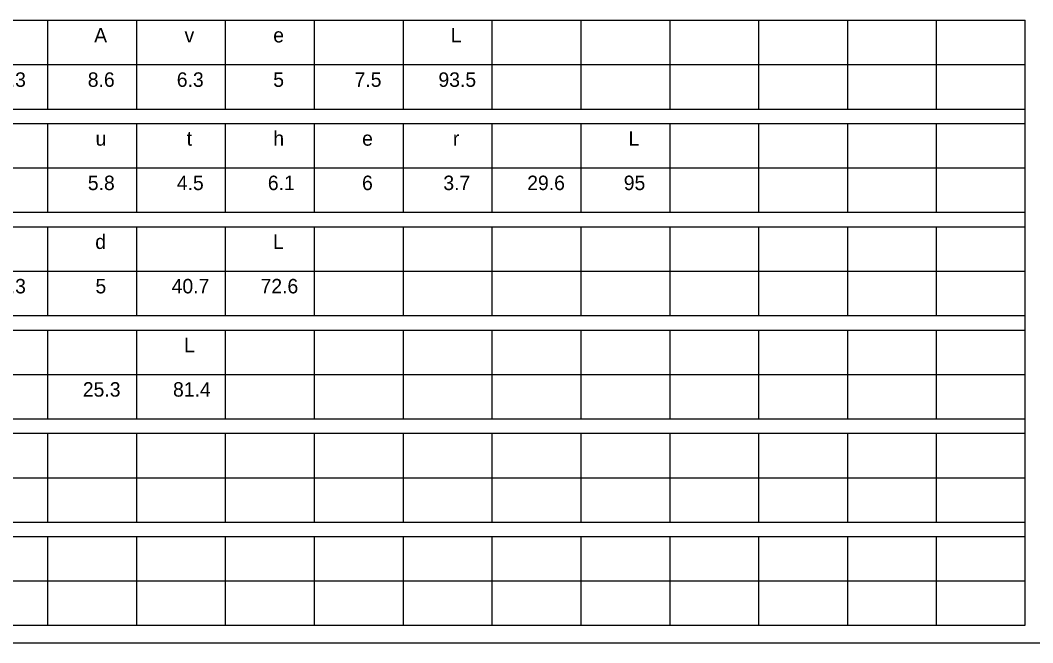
# Model space of a CAD drawing. Extents: x 1274.1 to 1363.1, y 833.5 to 890.6.
# Drawn here: x 1299.62 to 1318.48, y 864.21 to 875.81 of the extents above; entities that cross this region are included whole.
import ezdxf

# ---------------------------------------------------------------- set-up
doc = ezdxf.new("R2010")
doc.units = 0
doc.layers.add('GSSign', color=7, linetype='Continuous')
doc.layers.add('SheetLinesMisc2_dp', color=7, linetype='Continuous')

msp = doc.modelspace()

# ---------------------------------------------------------------- linework, layer by layer
at = {"layer": 'SheetLinesMisc2_dp'}
for p, q in [((1277.644, 875.806), (1318.336, 875.806)), ((1300.127, 875.806), (1300.127, 874.153)), ((1301.783, 875.806), (1301.783, 874.153)), ((1303.438, 875.806), (1303.438, 874.153)), ((1305.093, 875.806), (1305.093, 874.153)), ((1306.749, 875.806), (1306.749, 874.153)), ((1308.404, 875.806), (1308.404, 874.153)), ((1310.06, 875.806), (1310.06, 874.153)), ((1311.715, 875.806), (1311.715, 874.153)), ((1313.37, 875.806), (1313.37, 874.153)), ((1315.025, 875.806), (1315.025, 874.153)), ((1316.681, 875.806), (1316.681, 874.153)), ((1318.336, 864.539), (1318.336, 875.806)), ((1277.644, 874.979), (1318.336, 874.979)), ((1277.644, 874.153), (1318.336, 874.153)), ((1277.644, 873.883), (1318.336, 873.883)), ((1300.127, 873.883), (1300.127, 872.23)), ((1301.783, 873.883), (1301.783, 872.23)), ((1303.438, 873.883), (1303.438, 872.23)), ((1305.093, 873.883), (1305.093, 872.23)), ((1306.749, 873.883), (1306.749, 872.23)), ((1308.404, 873.883), (1308.404, 872.23)), ((1310.06, 873.883), (1310.06, 872.23)), ((1311.715, 873.883), (1311.715, 872.23)), ((1313.37, 873.883), (1313.37, 872.23)), ((1315.025, 873.883), (1315.025, 872.23)), ((1316.681, 873.883), (1316.681, 872.23)), ((1277.644, 873.056), (1318.336, 873.057)), ((1277.644, 872.23), (1318.336, 872.23)), ((1277.644, 871.96), (1318.336, 871.96)), ((1300.127, 871.96), (1300.127, 870.307)), ((1301.783, 871.96), (1301.783, 870.307)), ((1303.438, 871.96), (1303.438, 870.307)), ((1305.093, 871.96), (1305.093, 870.307)), ((1306.749, 871.96), (1306.749, 870.307)), ((1308.404, 871.96), (1308.404, 870.307)), ((1310.06, 871.96), (1310.06, 870.307)), ((1311.715, 871.96), (1311.715, 870.307)), ((1313.37, 871.96), (1313.37, 870.307)), ((1315.025, 871.96), (1315.025, 870.307)), ((1316.681, 871.96), (1316.681, 870.307)), ((1277.644, 871.134), (1318.336, 871.134)), ((1277.644, 870.307), (1318.336, 870.307)), ((1277.644, 870.038), (1318.336, 870.038)), ((1300.127, 870.038), (1300.127, 868.384)), ((1301.783, 870.038), (1301.783, 868.384)), ((1303.438, 870.038), (1303.438, 868.384)), ((1305.093, 870.038), (1305.093, 868.384)), ((1306.749, 870.038), (1306.749, 868.384)), ((1308.404, 870.038), (1308.404, 868.384)), ((1310.06, 870.038), (1310.06, 868.384)), ((1311.715, 870.038), (1311.715, 868.384)), ((1313.37, 870.038), (1313.37, 868.384)), ((1315.025, 870.038), (1315.025, 868.384)), ((1316.681, 870.038), (1316.681, 868.384)), ((1277.644, 869.211), (1318.336, 869.211)), ((1277.644, 868.384), (1318.336, 868.384)), ((1277.644, 868.115), (1318.336, 868.115)), ((1300.127, 868.115), (1300.127, 866.462)), ((1301.783, 868.115), (1301.783, 866.462)), ((1303.438, 868.115), (1303.438, 866.462)), ((1305.093, 868.115), (1305.093, 866.462)), ((1306.749, 868.115), (1306.749, 866.462)), ((1308.404, 868.115), (1308.404, 866.462)), ((1310.06, 868.115), (1310.06, 866.462)), ((1311.715, 868.115), (1311.715, 866.462)), ((1313.37, 868.115), (1313.37, 866.462)), ((1315.025, 868.115), (1315.025, 866.462)), ((1316.681, 868.115), (1316.681, 866.462)), ((1277.644, 867.288), (1318.336, 867.288)), ((1277.644, 866.462), (1318.336, 866.462)), ((1277.644, 866.192), (1318.336, 866.192)), ((1300.127, 866.192), (1300.127, 864.539)), ((1301.783, 866.192), (1301.783, 864.539)), ((1303.438, 866.192), (1303.438, 864.539)), ((1305.093, 866.192), (1305.093, 864.539)), ((1306.749, 866.192), (1306.749, 864.539)), ((1308.404, 866.192), (1308.404, 864.539)), ((1310.06, 866.192), (1310.06, 864.539)), ((1311.715, 866.192), (1311.715, 864.539)), ((1313.37, 866.192), (1313.37, 864.539)), ((1315.025, 866.192), (1315.025, 864.539)), ((1316.681, 866.192), (1316.681, 864.539)), ((1277.644, 865.366), (1318.336, 865.366)), ((1277.644, 864.539), (1318.336, 864.539)), ((1277.247, 864.214), (1359.988, 864.214))]:
    msp.add_line(p, q, dxfattribs=at)

# ---------------------------------------------------------------- texts
at = {"layer": 'GSSign'}
for s, height, p in [('A', 0.27, (1300.995, 875.393)), ('e', 0.27, (1304.33, 875.393)), ('L', 0.27, (1307.637, 875.393)), ('v', 0.27, (1302.679, 875.393)), ('8.3', 0.2696, (1299.222, 874.566)), ('8.6', 0.2696, (1300.876, 874.566)), ('6.3', 0.2696, (1302.534, 874.566)), ('5', 0.27, (1304.33, 874.566)), ('7.5', 0.2696, (1305.845, 874.566)), ('93.5', 0.2696, (1307.407, 874.566)), ('t', 0.27, (1302.718, 873.47)), ('h', 0.27, (1304.332, 873.47)), ('L', 0.27, (1310.948, 873.47)), ('u', 0.27, (1301.021, 873.47)), ('e', 0.27, (1305.986, 873.47)), ('r', 0.27, (1307.676, 873.47)), ('5.8', 0.2696, (1300.877, 872.643)), ('4.5', 0.2696, (1302.534, 872.643)), ('6.1', 0.2696, (1304.23, 872.643)), ('6', 0.27, (1305.984, 872.643)), ('3.7', 0.2696, (1307.499, 872.643)), ('29.6', 0.2696, (1309.061, 872.643)), ('95', 0.2696, (1310.859, 872.643)), ('d', 0.27, (1301.015, 871.547)), ('L', 0.27, (1304.325, 871.547)), ('6.3', 0.2696, (1299.222, 870.72)), ('5', 0.27, (1301.019, 870.72)), ('40.7', 0.2696, (1302.438, 870.72)), ('72.6', 0.2696, (1304.094, 870.72)), ('L', 0.27, (1302.67, 869.624)), ('25.3', 0.2696, (1300.784, 868.797)), ('81.4', 0.2696, (1302.464, 868.797))]:
    msp.add_text(s, height=height, dxfattribs=at).set_placement(p)

doc.saveas('drawing.dxf')
